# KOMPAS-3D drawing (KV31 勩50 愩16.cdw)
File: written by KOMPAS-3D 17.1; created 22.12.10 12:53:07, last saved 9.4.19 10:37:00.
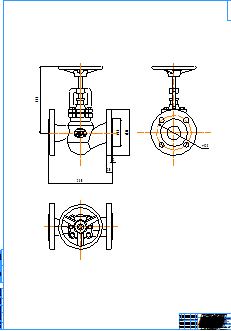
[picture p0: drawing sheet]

Title block, sheet 1: name: KV31 Ду50 Ру16; material: Внимание! Данный продукт является объектом авторского права ООО «Торговый Дом АДЛ». / Запрещается изменение, копирование, распространение / (в том числе путем копирования на другие сайты и ресурсы в Интернете) / или любое иное использование информации и объектов без предварительного / согласия правообладателя (ООО «Торговый Дом АДЛ»).; mass: 13; scale: 1:1; sheets: 1; organisation: ООО "Торговый дом АДЛ"; sheet format: A0; stored path: \\adlc.lan\data\АДЛ_ПКД\3D-модели\ADL production\Вентили ГРАНВЕНТ\KV31\KOMPAS 2D\KV31 Ду50.cdw

Views: Спереди 1, Проекционный вид 2, Проекционный вид 3
Dimensions and other numbers on the sheet: 2; 20; 230; 99; 165; 239; 125; 1:1; 1; 13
